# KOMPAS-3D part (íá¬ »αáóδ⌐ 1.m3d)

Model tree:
1. Эскиз:1
2. Операция выдавливания:1
     Расстояние 1 = 11
3. Эскиз:2
4. Вырезать элемент выдавливания:1
     Расстояние 1 = 34.7835
5. Скругление:1
     Радиус = 1
6. Скругление:2
     Радиус = 2
7. Эскиз:3
8. Вырезать элемент выдавливания:2
     Расстояние 1 = 0.2
9. Скругление:3
     Радиус = 0.1
10. Эскиз:4
11. Вырезать элемент выдавливания:3
     Расстояние 1 = 0.2
12. Скругление:4
     Радиус = 0.1
13. Эскиз:5
14. Операция выдавливания:2
     Расстояние 1 = 0.5; Расстояние 2 = 4.9
15. Скругление:5
     Радиус = 0.2
16. Эскиз:6
17. Операция выдавливания:3
     Расстояние 1 = 0.5; Расстояние 2 = 4.9

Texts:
  бак правый 1
  Сплав АЛ8  ГОСТ 1583-93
